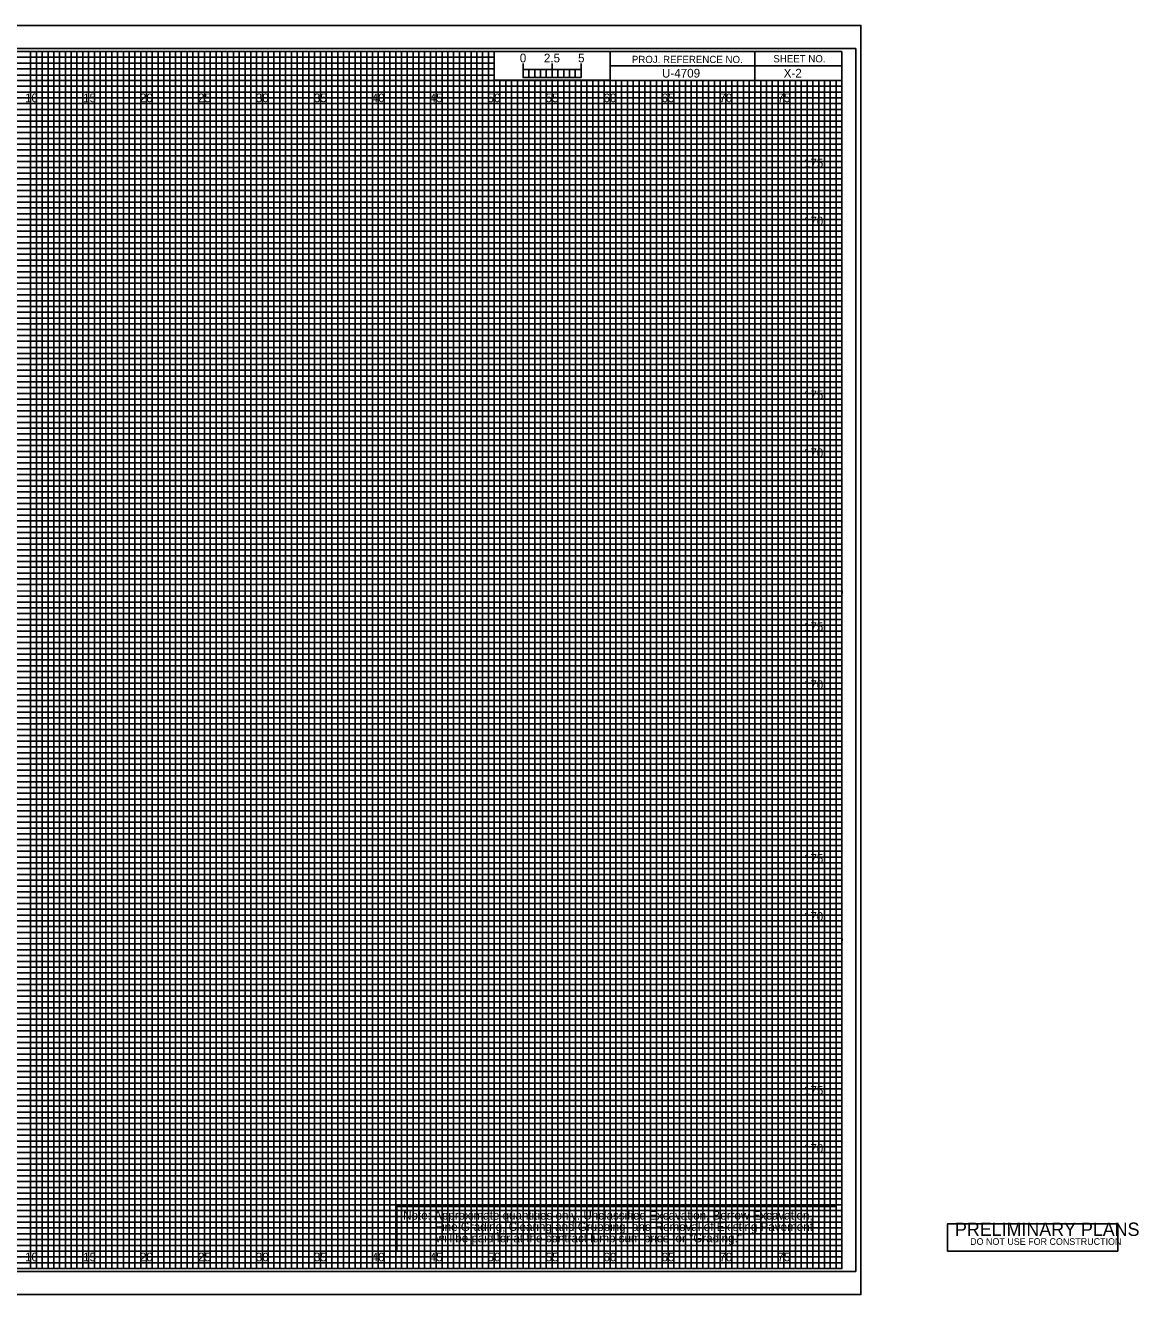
# Model space of a CAD drawing. Extents: x -7 to 186, y -2 to 107.
# Drawn here: x 89.5 to 185.6, y -2.3 to 107.3 of the extents above; entities that cross this region are included whole.
import ezdxf

# ---------------------------------------------------------------- set-up
doc = ezdxf.new("R2010")
doc.units = 0
for name, color, linetype in [('Prop Grid Mask', 7, 'Continuous'), ('Prop XS Bar Scale Labels', 7, 'Continuous'), ('Prop XS Elevation Labels', 7, 'Continuous'), ('Prop XS Offset Labels', 7, 'Continuous'), ('Prop XS Project Number', 7, 'Continuous'), ('Prop XS Sheet Number', 7, 'Continuous'), ('Prop XSC Text', 7, 'Continuous'), ('Sheet Cross Section CELL', 7, 'Continuous'), ('Sheet Cross Section Grid Major CELL', 7, 'Continuous'), ('Sheet Cross Section Grid Middle CELL', 7, 'Continuous'), ('Sheet Cross Section Grid Minor 1 CELL', 7, 'Continuous'), ('Sheet Cross Section Grid Minor 2 CELL', 7, 'Continuous'), ('Sheet Cross Section Scale CELL', 7, 'Continuous'), ('Sheet Cutting Line CELL', 7, 'Continuous'), ('Sheet DOT Grid CELL', 7, 'Continuous'), ('Sheet Plot Border Inside CELL', 7, 'Continuous'), ('Sheet Plot Border Outside CELL', 7, 'Continuous'), ('Sheet Sticker Preliminary CELL', 7, 'Continuous')]:
    doc.layers.add(name, color=color, linetype=linetype)

msp = doc.modelspace()

# ---------------------------------------------------------------- linework, layer by layer
at = {"layer": 'Prop Grid Mask'}
msp.add_lwpolyline([(121.61, 5.34), (159.5, 5.34), (159.5, 1.5), (121.61, 1.5)], close=True, dxfattribs=at)
at = {"layer": 'Sheet Cross Section CELL'}
for p, q in [((152.5, 105), (152.5, 102.5)), ((152.5, 102.5), (152.5, 105)), ((160, 103.75), (140, 103.75)), ((140, 103.75), (140, 102.5)), ((140, 102.5), (160, 102.5))]:
    msp.add_line(p, q, dxfattribs=at)
for points in [[(160, 105), (0, 105), (0, 0), (160, 0)], [(140, 105), (130, 105), (130, 102.52), (140, 102.52)], [(160, 105), (140, 105), (140, 102.5), (160, 102.5)]]:
    msp.add_lwpolyline(points, close=True, dxfattribs=at)
at = {"layer": 'Sheet Cross Section Grid Major CELL'}
for p, q in [((95, 105), (90, 105)), ((90, 105), (90, 0)), ((95, 0), (95, 105)), ((105, 105), (100, 105)), ((100, 105), (100, 0)), ((105, 0), (105, 105)), ((115, 105), (110, 105)), ((110, 105), (110, 0)), ((115, 0), (115, 105)), ((125, 105), (120, 105)), ((120, 105), (120, 0)), ((125, 0), (125, 105)), ((130, 105), (130, 0)), ((135, 0), (135, 102.5)), ((145, 102.5), (140, 102.5)), ((140, 102.5), (140, 0)), ((145, 0), (145, 102.5)), ((155, 102.5), (150, 102.5)), ((150, 102.5), (150, 0)), ((155, 0), (155, 102.5)), ((90, 0), (85, 0)), ((100, 0), (95, 0)), ((110, 0), (105, 0)), ((120, 0), (115, 0)), ((130, 0), (125, 0)), ((140, 0), (135, 0)), ((150, 0), (145, 0)), ((160, 0), (155, 0)), ((160, 0), (160, 0))]:
    msp.add_line(p, q, dxfattribs=at)
for points in [[(0, 100), (160, 100), (160, 95), (0, 95)], [(0, 90), (160, 90), (160, 85), (0, 85)], [(0, 80), (160, 80), (160, 75), (0, 75)], [(0, 70), (160, 70), (160, 65), (0, 65)], [(0, 60), (160, 60), (160, 55), (0, 55)], [(0, 50), (160, 50), (160, 45), (0, 45)], [(0, 40), (160, 40), (160, 35), (0, 35)], [(0, 30), (160, 30), (160, 25), (0, 25)], [(0, 20), (160, 20), (160, 15), (0, 15)], [(0, 10), (160, 10), (160, 5), (0, 5)]]:
    msp.add_lwpolyline(points, dxfattribs=at)
at = {"layer": 'Sheet Cross Section Grid Middle CELL'}
for points in [[(87.5, 105), (92.5, 105), (92.5, 0), (97.5, 0), (97.5, 105), (102.5, 105), (102.5, 0), (107.5, 0), (107.5, 105), (112.5, 105), (112.5, 0), (117.5, 0), (117.5, 105), (122.5, 105), (122.5, 0), (127.5, 0), (127.5, 105), (129.97, 105), (130, 105), (130, 102.5), (132.5, 102.5), (132.5, 0), (137.5, 0), (137.5, 102.5), (142.5, 102.5), (142.5, 0), (147.5, 0), (147.5, 102.5), (152.5, 102.5), (152.5, 0), (157.5, 0), (157.5, 102.5)], [(0, 102.5), (137.5, 102.5)], [(0, 92.5), (160, 92.5), (160, 97.5), (0, 97.5)], [(0, 82.5), (160, 82.5), (160, 87.5), (0, 87.5)], [(0, 72.5), (160, 72.5), (160, 77.5), (0, 77.5)], [(0, 62.5), (160, 62.5), (160, 67.5), (0, 67.5)], [(0, 52.5), (160, 52.5), (160, 57.5), (0, 57.5)], [(0, 42.5), (160, 42.5), (160, 47.5), (0, 47.5)], [(0, 32.5), (160, 32.5), (160, 37.5), (0, 37.5)], [(0, 22.5), (160, 22.5), (160, 27.5), (0, 27.5)], [(0, 12.5), (160, 12.5), (160, 17.5), (0, 17.5)], [(0, 2.5), (160, 2.5), (160, 7.5), (0, 7.5)]]:
    msp.add_lwpolyline(points, dxfattribs=at)
at = {"layer": 'Sheet Cross Section Grid Minor 1 CELL'}
for p, q in [((0, 104.5), (130, 104.5)), ((130, 104.5), (130, 103.99)), ((130, 103.99), (0, 103.99)), ((0, 103.5), (130, 103.5)), ((130, 102.95), (0, 102.95)), ((130, 103.5), (130, 102.95)), ((0, 102), (160, 102))]:
    msp.add_line(p, q, dxfattribs=at)
for points in [[(0, 101.5), (135, 101.5), (160, 101.5), (160, 101), (0, 101)], [(0, 100.5), (160, 100.5), (160, 99.5), (0, 99.5)], [(0, 99), (160, 99), (160, 98.5), (0, 98.49)], [(0, 98), (160, 98), (160, 97), (0, 97)], [(0, 96.5), (160, 96.5), (160, 96), (0, 96)], [(0, 95.5), (160, 95.5), (160, 94.5), (0, 94.5)], [(0, 94), (160, 94), (160, 93.5), (0, 93.5)], [(0, 93), (160, 93), (160, 92), (0, 92)], [(0, 91.5), (160, 91.5), (160, 91), (0, 91)], [(0, 90.5), (160, 90.5), (160, 89.5), (0, 89.5)], [(0, 89), (160, 89), (160, 88.5), (0, 88.5)], [(0, 88), (160, 88), (160, 86.98), (160, 86.5), (160, 86), (0, 86)], [(0, 87), (160, 87), (160, 86.5), (0, 86.5)], [(0, 85.5), (160, 85.5), (160, 84.5), (0, 84.52)], [(0, 84.52), (160, 84.5), (160, 84), (0, 84)], [(0, 83.5), (160, 83.5), (160, 83), (0, 83)], [(0, 82), (160, 82), (160, 81.5), (0, 81.5)], [(0, 81), (160, 81), (160, 80.5), (0, 80.5)], [(-0.04, 79.45), (160, 79.45), (160, 78.94), (-0.04, 78.94)], [(0, 78.5), (160, 78.5), (160, 78), (0, 78)], [(0, 77), (160, 77), (160, 76.5), (0, 76.5)], [(0, 76), (160, 76), (160, 75.5), (0, 75.5)], [(0, 74.5), (160, 74.5), (160, 74), (0, 74)], [(0, 73.5), (160, 73.5), (160, 73), (0, 73)], [(0, 72), (160, 72), (160, 71.5), (0, 71.5)], [(0, 71), (160, 71), (160, 70.5), (0, 70.5)], [(0, 69.5), (160, 69.5), (160, 68.99), (0, 69)], [(0, 68.5), (160, 68.5), (160, 68), (0, 68)], [(0, 67), (160, 67), (160, 66.5), (0, 66.5)], [(0, 66), (160, 66), (160, 65.5), (0, 65.5)], [(0, 64.5), (160, 64.5), (160, 64), (0, 64)], [(0, 63.5), (160, 63.5), (160, 63), (0, 63)], [(0, 62), (160, 62), (160, 61.5), (0, 61.5)], [(0, 61), (160, 61), (160, 60.5), (0, 60.5)], [(0, 59.5), (160, 59.5), (160, 59), (0, 59)], [(0, 58.5), (160.03, 58.45), (160, 58), (0, 58)], [(0, 57), (160, 57), (160, 56.5), (0, 56.5)], [(0, 56), (160, 56), (160, 55.5), (0, 55.5)], [(0, 54.5), (160, 54.5), (160, 54), (0, 54)], [(0, 53.5), (160, 53.5), (160, 53), (0, 53)], [(0, 52), (160, 52), (160, 51.5), (0, 51.5)], [(0, 51), (160, 51), (160, 50.5), (0, 50.5)], [(0, 49.5), (160, 49.5), (160, 49), (0, 49)], [(0, 48.5), (160, 48.5), (160, 48), (0, 48)], [(0, 47), (160, 47), (160, 46.5), (0, 46.5)], [(0, 46), (160, 46), (160, 45.5), (0, 45.5)], [(0, 44.5), (160, 44.5), (160, 44), (0, 44)], [(0, 43.5), (160, 43.5), (160, 43), (0, 43)], [(0, 42), (160, 42), (160, 41.5), (0, 41.5)], [(0, 41), (160, 41), (160, 40.5), (0, 40.5)], [(0, 39.5), (160, 39.5), (160, 38.99), (0, 39)], [(0, 38.5), (160, 38.5), (160, 38), (0, 38)], [(0, 37), (160, 37), (160, 36.5), (0, 36.5)], [(0, 36), (160, 36), (160, 35.5), (0, 35.5)], [(0, 34.5), (160, 34.5), (160, 34), (0, 34)], [(0, 33.5), (160, 33.5), (160, 33), (0, 33)], [(0, 32), (160, 32), (160, 31.5), (0, 31.5)], [(0, 31), (160, 31), (160, 30.5), (0, 30.5)], [(0, 29.5), (160, 29.5), (160, 29), (0, 29)], [(0, 28.5), (160.03, 28.46), (160, 28), (0, 28)], [(0, 27), (160, 27), (160, 26.5), (0, 26.5)], [(0, 26), (160, 26), (160, 25.5), (0, 25.5)], [(0, 24.5), (160, 24.5), (160, 24), (0, 24)], [(0, 23.5), (160, 23.5), (160, 23), (0, 23)], [(0, 22), (160, 22), (160, 21.5), (0, 21.5)], [(0, 21), (160, 21), (160, 20.5), (0, 20.5)], [(0, 19.5), (160, 19.5), (160, 19), (0, 19)], [(0, 18.5), (160, 18.5), (160, 18), (0, 18)], [(0, 17), (160, 17), (160, 16.5), (0, 16.5)], [(0, 16), (160, 16), (160, 15.5), (0, 15.5)], [(0, 14.5), (160, 14.5), (160, 14), (0, 14)], [(0, 13.5), (160, 13.5), (160, 13), (0, 13)], [(0, 12), (160, 12), (160, 11.5), (0, 11.5)], [(0, 11), (160, 11), (160, 10.5), (0, 10.5)], [(0, 9.5), (160, 9.5), (160, 9), (0, 9)], [(0, 8.5), (160, 8.5), (160, 8), (0, 8)], [(0, 7), (160, 7), (160, 6.5), (0, 6.5)], [(0, 6), (160, 6), (160, 5.5), (0, 5.5)], [(0, 4.5), (160, 4.5), (160, 4), (0, 4)], [(0, 3.5), (160, 3.5), (160, 3), (0, 3)], [(0, 2), (160, 2), (160, 1.5), (0, 1.5)], [(0, 1), (160, 1), (160, 0.5), (0, 0.5)]]:
    msp.add_lwpolyline(points, dxfattribs=at)
at = {"layer": 'Sheet Cross Section Grid Minor 2 CELL'}
for p, q in [((133.5, 102.5), (133, 102.5)), ((133, 102.5), (133, 0)), ((133.5, 0), (133.5, 102.5)), ((134.5, 102.5), (134, 102.5)), ((134, 102.5), (134, 0)), ((134.5, 0), (134.5, 102.5)), ((133, 0), (132.5, 0)), ((134, 0), (133.5, 0))]:
    msp.add_line(p, q, dxfattribs=at)
for points in [[(90, 0), (90.5, 0), (90.5, 105), (91, 105), (91, 0)], [(91, 0), (91.5, 0), (91.5, 105), (92, 105), (92, 0)], [(92.5, 0), (93, 0), (93, 105), (93.5, 105), (93.5, 0)], [(93.5, 0), (94, 0), (94, 105), (94.5, 105), (94.5, 0)], [(95, 0), (95.5, 0), (95.5, 105), (96, 105), (96, 0)], [(96, 0), (96.5, 0), (96.5, 105), (97, 105), (97, 0)], [(97.5, 0), (98, 0), (98, 105), (98.5, 105), (98.5, 0)], [(98.5, 0), (99, 0), (99, 105), (99.5, 105), (99.5, 0)], [(100, 0), (100.5, 0), (100.5, 105), (101, 105), (101, 0)], [(101, 0), (101.5, 0), (101.5, 105), (102, 105), (102, 0)], [(102.5, 0), (103, 0), (103, 105), (103.5, 105), (103.5, 0)], [(103.5, 0), (104, 0), (104, 105), (104.5, 105), (104.5, 0)], [(105, 0), (105.5, 0), (105.5, 105), (106, 105), (106, 0)], [(106, 0), (106.5, 0), (106.5, 105), (107, 105), (107, 0)], [(107.5, 0), (108, 0), (108, 105), (108.5, 105), (108.5, 0)], [(108.5, 0), (109, 0), (109, 105), (109.5, 105), (109.5, 0)], [(110, 0), (110.5, 0), (110.5, 105), (111, 105), (111, 0)], [(111, 0), (111.5, 0), (111.5, 105), (112, 105), (112, 0)], [(112.5, 0), (113, 0), (113, 105), (113.5, 105), (113.5, 0)], [(113.5, 0), (114, 0), (114, 105), (114.5, 105), (114.5, 0)], [(115, 0), (115.5, 0), (115.5, 105), (116, 105), (116, 0)], [(116, 0), (116.5, 0), (116.5, 105), (117, 105), (117, 0)], [(117.5, 0), (118, 0), (118, 105), (118.5, 105), (118.5, 0)], [(118.5, 0), (119, 0), (119, 105), (119.5, 105), (119.5, 0)], [(120, 0), (120.5, 0), (120.5, 105), (121, 105), (121, 0)], [(121, 0), (121.5, 0), (121.5, 105), (122, 105), (122, 0)], [(122.5, 0), (123, 0), (123, 105), (123.5, 105), (123.5, 0)], [(123.5, 0), (124, 0), (124, 105), (124.5, 105), (124.5, 0)], [(125, 0), (125.5, 0), (125.5, 105), (126, 105), (126, 0)], [(126, 0), (126.5, 0), (126.5, 105), (127, 105), (127, 0)], [(127.5, 0), (128, 0), (128, 105), (128.5, 105), (128.5, 0)], [(128.5, 0), (129, 0), (129, 105), (129.5, 105), (129.5, 0)], [(130, 0), (130.5, 0), (130.5, 102.5), (131.01, 102.5), (131.01, 0)], [(131, 0), (131.5, 0), (131.5, 102.5), (132, 102.5), (132, 0)], [(135, 0), (135.49, 0), (135.49, 102.5), (136, 102.5), (136, 0)], [(136, 0), (136.5, 0), (136.5, 102.5), (137.03, 102.5), (137.03, 0)], [(137.5, 0), (138, 0), (138, 102.5), (138.5, 102.5), (138.5, 0)], [(138.5, 0), (139, 0), (139, 102.5), (139.5, 102.5), (139.5, 0)], [(140, 0), (140.5, 0), (140.5, 102.5), (141, 102.5), (141, 0)], [(141, 0), (141.5, 0), (141.5, 102.5), (142, 102.5), (142, 0)], [(142.5, 0), (143, 0), (143, 102.5), (143.5, 102.5), (143.5, 0)], [(143.5, 0), (144, 0), (144, 102.5), (144.5, 102.5), (144.5, 0)], [(145, 0), (145.5, 0), (145.5, 102.5), (146, 102.5), (146, 0)], [(146, 0), (146.5, 0), (146.5, 102.5), (147, 102.5), (147, 0)], [(147.5, 0), (148, 0), (148, 102.5), (148.5, 102.5), (148.5, 0)], [(148.5, 0), (149, 0), (149, 102.5), (149.5, 102.5), (149.5, 0)], [(150, 0), (150.5, 0), (150.5, 102.5), (151, 102.5), (151, 0)], [(151, 0), (151.5, 0), (151.5, 102.5), (152, 102.5), (152, 0)], [(152.5, 0), (153, 0), (153, 102.5), (153.5, 102.5), (153.5, 0)], [(153.5, 0), (154, 0), (154, 102.5), (154.5, 102.5), (154.5, 0)], [(155, 0), (155.5, 0), (155.5, 102.5), (156, 102.5), (156, 0)], [(156, 0), (156.5, 0), (156.5, 102.5), (157, 102.5), (157, 0)], [(157.5, 0), (158, 0), (158, 102.5), (158.5, 102.5), (158.5, 0)], [(158.5, 0), (159, 0), (159, 102.5), (159.5, 102.5), (159.5, 0)]]:
    msp.add_lwpolyline(points, dxfattribs=at)
at = {"layer": 'Sheet Cross Section Scale CELL'}
for p, q in [((132.5, 102.75), (132.5, 103.95)), ((132.5, 103.45), (132.5, 103.95)), ((135, 102.75), (135, 103.95)), ((137.5, 102.75), (137.5, 103.95)), ((137.5, 103.45), (137.5, 103.95))]:
    msp.add_line(p, q, dxfattribs=at)
for points in [[(137.5, 103.45), (132.5, 103.45), (132.5, 102.75), (137.5, 102.75)], [(132.5, 103.45), (133, 103.45), (133, 102.75), (132.5, 102.75)], [(133.5, 103.45), (134, 103.45), (134, 102.75), (133.5, 102.75)], [(134.5, 103.45), (135, 103.45), (135, 102.75), (134.5, 102.75)], [(135.5, 103.45), (136, 103.45), (136, 102.75), (135.5, 102.75)], [(136.5, 103.45), (137, 103.45), (137, 102.75), (136.5, 102.75)]]:
    msp.add_lwpolyline(points, close=True, dxfattribs=at)
at = {"layer": 'Sheet Cutting Line CELL'}
for p, q in [((161.65, 107.25), (-6.7, 107.25)), ((-6.7, -2.25), (161.65, -2.25))]:
    msp.add_line(p, q, dxfattribs=at)
at = {"layer": 'Sheet DOT Grid CELL'}
for p, q in [((90, 0), (90, 105)), ((95, 0), (95, 105)), ((100, 0), (100, 105)), ((105, 0), (105, 105)), ((110, 0), (110, 105)), ((115, 0), (115, 105)), ((120, 0), (120, 105)), ((125, 0), (125, 105)), ((130, 0), (130, 102.34)), ((135, 0), (135, 102.34)), ((140, 0), (140, 102.34)), ((145, 0), (145, 102.34)), ((150, 0), (150, 102.34)), ((155, 0), (155, 102.34)), ((0, 100), (160, 100)), ((0, 95), (160, 95)), ((0, 90), (160, 90)), ((0, 85), (160, 85)), ((0, 80), (160, 80)), ((0, 75), (160, 75)), ((0, 70), (160, 70)), ((0, 65), (160, 65)), ((0, 60), (160, 60)), ((0, 55), (160, 55)), ((0, 50), (160, 50)), ((0, 45), (160, 45)), ((0, 40), (160, 40)), ((0, 35), (160, 35)), ((0, 30), (160, 30)), ((0, 25), (160, 25)), ((0, 20), (160, 20)), ((0, 15), (160, 15)), ((0, 10), (160, 10)), ((0, 5), (160, 5))]:
    msp.add_line(p, q, dxfattribs=at)
at = {"layer": 'Sheet Plot Border Inside CELL'}
msp.add_lwpolyline([(-5.4, -0.25), (161.2, -0.25), (161.2, 105.25), (-5.4, 105.25)], close=True, dxfattribs=at)
at = {"layer": 'Sheet Plot Border Outside CELL'}
msp.add_lwpolyline([(-6.7, -2.25), (161.65, -2.25), (161.65, 107.25), (-6.7, 107.25)], close=True, dxfattribs=at)
at = {"layer": 'Sheet Sticker Preliminary CELL'}
msp.add_lwpolyline([(169.11, 1.5), (169.11, 3.85), (183.81, 3.85), (183.81, 1.5)], close=True, dxfattribs=at)

# ---------------------------------------------------------------- texts
at = {"layer": 'Prop XS Bar Scale Labels'}
for s, p in [('2.5', (134.29, 104.06)), ('5', (137.24, 104.06))]:
    msp.add_text(s, height=0.75, dxfattribs=at).set_placement(p)
at = {"layer": 'Prop XS Elevation Labels'}
for s, p in [('175', (156.73, 95)), ('170', (156.72, 90)), ('175', (156.73, 75)), ('170', (156.72, 70)), ('175', (156.73, 55)), ('170', (156.72, 50)), ('175', (156.73, 35)), ('170', (156.72, 30)), ('175', (156.73, 15)), ('170', (156.72, 10))]:
    msp.add_text(s, height=0.75, dxfattribs=at).set_placement(p)
at = {"layer": 'Prop XS Offset Labels'}
for s, p in [('10', (89.52, 100.62)), ('15', (94.53, 100.62)), ('20', (99.43, 100.62)), ('25', (104.44, 100.62)), ('30', (109.43, 100.62)), ('35', (114.44, 100.62)), ('40', (119.43, 100.62)), ('45', (124.44, 100.62)), ('50', (129.43, 100.62)), ('55', (134.44, 100.62)), ('60', (139.43, 100.62)), ('65', (144.44, 100.62)), ('70', (149.43, 100.62)), ('75', (154.44, 100.62)), ('10', (89.52, 0.62)), ('15', (94.53, 0.62)), ('20', (99.43, 0.62)), ('25', (104.44, 0.62)), ('30', (109.43, 0.62)), ('35', (114.44, 0.62)), ('40', (119.43, 0.62)), ('45', (124.44, 0.62)), ('50', (129.43, 0.62)), ('55', (134.44, 0.62)), ('60', (139.43, 0.62)), ('65', (144.44, 0.62)), ('70', (149.43, 0.62)), ('75', (154.44, 0.62))]:
    msp.add_text(s, height=0.75, dxfattribs=at).set_placement(p)
at = {"layer": 'Prop XS Project Number'}
msp.add_text('U-4709', height=0.75, dxfattribs=at).set_placement((144.48, 102.75))
at = {"layer": 'Prop XS Sheet Number'}
msp.add_text('X-2', height=0.75, dxfattribs=at).set_placement((154.98, 102.75))
at = {"layer": 'Prop XSC Text'}
for s, p in [('Note: Approximate quantities only. Unclassified Excavation, Borrow Excavation, ', (122.14, 4.22)), ('Fine Grading, Clearing and Grubbing, and Removal of Existing Pavement', (124.89, 3.24)), ('will be paid for at the contract lump sum price for "Grading."', (124.97, 2.26))]:
    msp.add_text(s, height=0.75, dxfattribs=at).set_placement(p)
at = {"layer": 'Sheet Cross Section CELL'}
for s, p in [('PROJ. REFERENCE NO.', (141.88, 104)), ('SHEET NO.', (154.09, 104.06))]:
    msp.add_text(s, height=0.625, dxfattribs=at).set_placement(p)
at = {"layer": 'Sheet Cross Section Scale CELL'}
msp.add_text('0', height=0.75, dxfattribs=at).set_placement((132.21, 104.06))
at = {"layer": 'Sheet Sticker Preliminary CELL'}
for s, height, p in [('PRELIMINARY PLANS', 1.152, (169.76, 2.81)), ('DO NOT USE FOR CONSTRUCTION', 0.576, (171.07, 2.04))]:
    msp.add_text(s, height=height, dxfattribs=at).set_placement(p)

doc.saveas('drawing.dxf')
